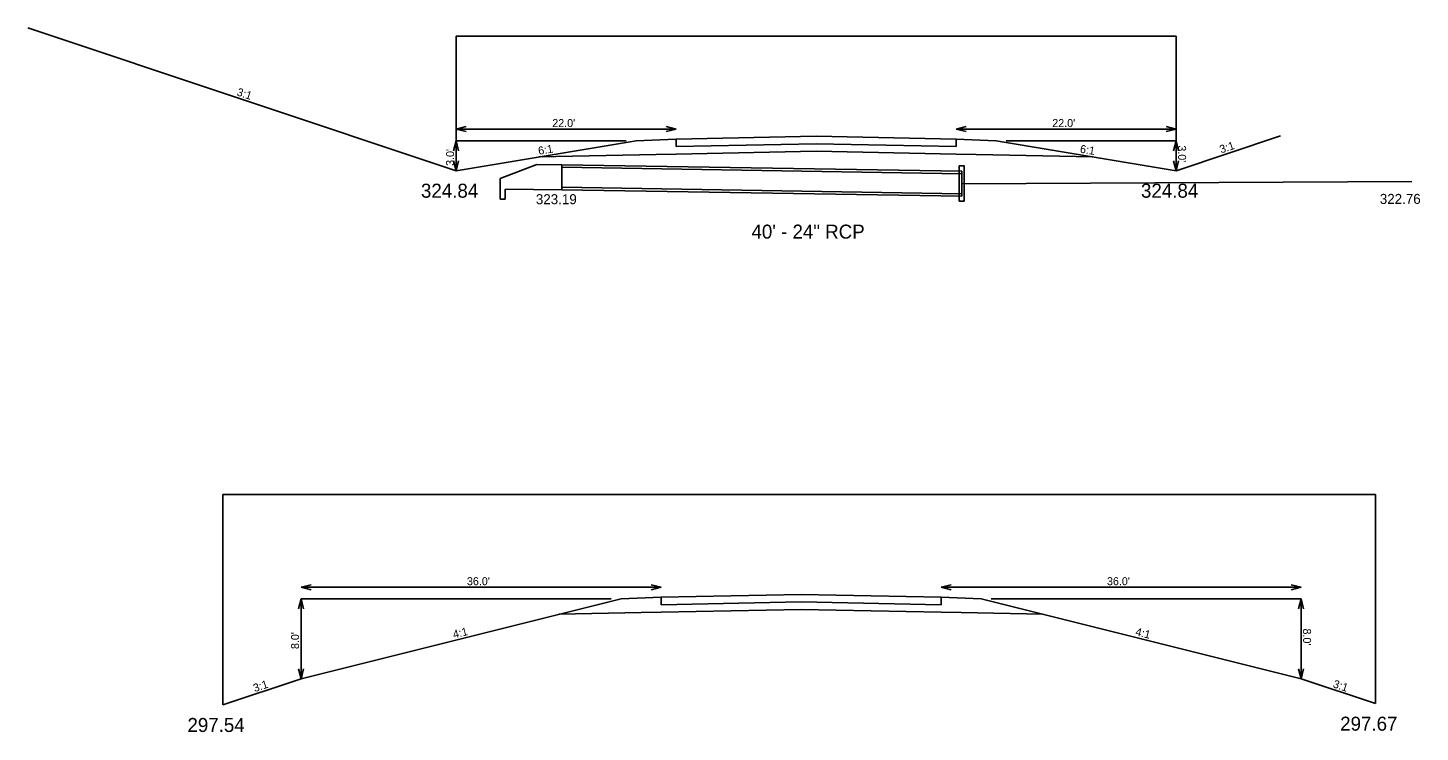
# Model space of a CAD drawing. Extents: x 2432865 to 2441203, y 1814550 to 1826842.
# Drawn here: x 2441063.6 to 2441202.8, y 1814889.3 to 1814959.7 of the extents above; entities that cross this region are included whole.
import ezdxf

# ---------------------------------------------------------------- set-up
doc = ezdxf.new("R2010")
doc.units = 0
for name, color, linetype in [('Default', 7, 'Continuous'), ('X_DRAINAGE_PIPES', 7, 'Continuous'), ('XS_M_DITCH', 7, 'Continuous'), ('XS_P_DRAINAGE', 7, 'Continuous'), ('XS_P_FINISHED_GRADE', 7, 'Continuous'), ('XS_P_SUBGRADE_GRANULAR', 7, 'Continuous'), ('XS_P_SUBGRADE_PAVEMENT', 7, 'Continuous'), ('XS_P_TX_CLEARZONE', 7, 'Continuous'), ('XS_P_TX_DCH', 7, 'Continuous'), ('XS_P_TX_FS_BS', 7, 'Continuous')]:
    doc.layers.add(name, color=color, linetype=linetype)

msp = doc.modelspace()

# ---------------------------------------------------------------- linework, layer by layer
at = {"layer": 'X_DRAINAGE_PIPES'}
msp.add_line((2441201.95, 1814944.3), (2441156.93, 1814944.08), dxfattribs=at)
at = {"layer": 'XS_M_DITCH'}
for p, q in [((2441106.37, 1814945.38), (2441106.37, 1814958.82)), ((2441106.37, 1814958.82), (2441178.37, 1814958.82)), ((2441106.37, 1814945.38), (2441106.37, 1814958.82)), ((2441106.37, 1814958.82), (2441178.37, 1814958.82)), ((2441178.37, 1814958.82), (2441178.37, 1814945.38)), ((2441178.37, 1814958.82), (2441178.37, 1814945.38)), ((2441083.04, 1814891.98), (2441083.04, 1814913.03)), ((2441083.04, 1814913.03), (2441198.3, 1814913.03)), ((2441083.04, 1814891.98), (2441083.04, 1814913.03)), ((2441083.04, 1814913.03), (2441198.3, 1814913.03)), ((2441198.3, 1814913.03), (2441198.3, 1814892.11)), ((2441198.3, 1814913.03), (2441198.3, 1814892.11))]:
    msp.add_line(p, q, dxfattribs=at)
at = {"layer": 'XS_P_DRAINAGE'}
for p, q in [((2441110.78, 1814944.6), (2441114.45, 1814946)), ((2441114.45, 1814946), (2441116.95, 1814945.98)), ((2441116.95, 1814945.98), (2441116.94, 1814943.48)), ((2441116.95, 1814945.98), (2441116.94, 1814943.48)), ((2441116.95, 1814945.98), (2441156.95, 1814945.33)), ((2441116.95, 1814945.73), (2441156.94, 1814945.08)), ((2441156.95, 1814945.33), (2441156.94, 1814942.83)), ((2441110.77, 1814942.52), (2441110.78, 1814944.6)), ((2441116.94, 1814943.73), (2441156.94, 1814943.08)), ((2441111.27, 1814942.52), (2441110.77, 1814942.52)), ((2441116.94, 1814943.48), (2441111.27, 1814943.52)), ((2441111.27, 1814943.52), (2441111.27, 1814942.52)), ((2441116.94, 1814943.48), (2441156.94, 1814942.83))]:
    msp.add_line(p, q, dxfattribs=at)
msp.add_lwpolyline([(2441156.68, 1814945.85), (2441157.18, 1814945.85), (2441157.18, 1814942.34), (2441156.68, 1814942.34)], close=True, dxfattribs=at)
at = {"layer": 'XS_P_FINISHED_GRADE'}
for p, q in [((2441106.37, 1814945.38), (2441063.55, 1814959.66)), ((2441106.37, 1814945.38), (2441063.55, 1814959.66)), ((2441124.37, 1814948.38), (2441106.37, 1814945.38)), ((2441124.37, 1814948.38), (2441106.37, 1814945.38)), ((2441128.37, 1814948.54), (2441124.37, 1814948.38)), ((2441128.37, 1814948.54), (2441124.37, 1814948.38)), ((2441128.37, 1814948.54), (2441142.37, 1814948.82)), ((2441128.37, 1814948.54), (2441142.37, 1814948.82)), ((2441142.37, 1814948.82), (2441156.37, 1814948.54)), ((2441142.37, 1814948.82), (2441156.37, 1814948.54)), ((2441156.37, 1814948.54), (2441160.37, 1814948.38)), ((2441156.37, 1814948.54), (2441160.37, 1814948.38)), ((2441160.37, 1814948.38), (2441178.37, 1814945.38)), ((2441160.37, 1814948.38), (2441178.37, 1814945.38)), ((2441178.37, 1814945.38), (2441188.81, 1814948.86)), ((2441178.37, 1814945.38), (2441188.81, 1814948.86)), ((2441122.87, 1814902.59), (2441090.87, 1814894.59)), ((2441122.87, 1814902.59), (2441090.87, 1814894.59)), ((2441126.87, 1814902.75), (2441122.87, 1814902.59)), ((2441126.87, 1814902.75), (2441122.87, 1814902.59)), ((2441126.87, 1814902.75), (2441140.87, 1814903.03)), ((2441126.87, 1814902.75), (2441140.87, 1814903.03)), ((2441140.87, 1814903.03), (2441154.87, 1814902.75)), ((2441140.87, 1814903.03), (2441154.87, 1814902.75)), ((2441154.87, 1814902.75), (2441158.87, 1814902.59)), ((2441154.87, 1814902.75), (2441158.87, 1814902.59)), ((2441158.87, 1814902.59), (2441190.87, 1814894.59)), ((2441158.87, 1814902.59), (2441190.87, 1814894.59)), ((2441090.87, 1814894.59), (2441083.04, 1814891.98)), ((2441090.87, 1814894.59), (2441083.04, 1814891.98)), ((2441190.87, 1814894.59), (2441198.3, 1814892.11)), ((2441190.87, 1814894.59), (2441198.3, 1814892.11))]:
    msp.add_line(p, q, dxfattribs=at)
at = {"layer": 'XS_P_SUBGRADE_GRANULAR'}
for p, q in [((2441126.37, 1814947), (2441114.69, 1814946.77)), ((2441126.37, 1814947), (2441114.69, 1814946.77)), ((2441128.37, 1814947.04), (2441126.37, 1814947)), ((2441128.37, 1814947.04), (2441126.37, 1814947)), ((2441128.37, 1814947.04), (2441142.37, 1814947.32)), ((2441128.37, 1814947.04), (2441142.37, 1814947.32)), ((2441142.37, 1814947.32), (2441156.37, 1814947.04)), ((2441142.37, 1814947.32), (2441156.37, 1814947.04)), ((2441156.37, 1814947.04), (2441158.37, 1814947)), ((2441156.37, 1814947.04), (2441158.37, 1814947)), ((2441158.37, 1814947), (2441170.06, 1814946.77)), ((2441158.37, 1814947), (2441170.06, 1814946.77)), ((2441124.87, 1814901.21), (2441116.69, 1814901.05)), ((2441124.87, 1814901.21), (2441116.69, 1814901.05)), ((2441126.87, 1814901.25), (2441124.87, 1814901.21)), ((2441126.87, 1814901.25), (2441124.87, 1814901.21)), ((2441126.87, 1814901.25), (2441140.87, 1814901.53)), ((2441126.87, 1814901.25), (2441140.87, 1814901.53)), ((2441140.87, 1814901.53), (2441154.87, 1814901.25)), ((2441140.87, 1814901.53), (2441154.87, 1814901.25)), ((2441154.87, 1814901.25), (2441156.87, 1814901.21)), ((2441154.87, 1814901.25), (2441156.87, 1814901.21)), ((2441156.87, 1814901.21), (2441165.04, 1814901.05)), ((2441156.87, 1814901.21), (2441165.04, 1814901.05))]:
    msp.add_line(p, q, dxfattribs=at)
at = {"layer": 'XS_P_SUBGRADE_PAVEMENT'}
for p, q in [((2441128.37, 1814947.79), (2441128.37, 1814948.54)), ((2441128.37, 1814947.79), (2441128.37, 1814948.54)), ((2441128.37, 1814947.79), (2441142.37, 1814948.07)), ((2441128.37, 1814947.79), (2441142.37, 1814948.07)), ((2441142.37, 1814948.07), (2441156.37, 1814947.79)), ((2441142.37, 1814948.07), (2441156.37, 1814947.79)), ((2441156.37, 1814947.79), (2441156.37, 1814948.54)), ((2441156.37, 1814947.79), (2441156.37, 1814948.54)), ((2441126.87, 1814902), (2441126.87, 1814902.75)), ((2441126.87, 1814902), (2441126.87, 1814902.75)), ((2441126.87, 1814902), (2441140.87, 1814902.28)), ((2441126.87, 1814902), (2441140.87, 1814902.28)), ((2441140.87, 1814902.28), (2441154.87, 1814902)), ((2441140.87, 1814902.28), (2441154.87, 1814902)), ((2441154.87, 1814902), (2441154.87, 1814902.75)), ((2441154.87, 1814902), (2441154.87, 1814902.75))]:
    msp.add_line(p, q, dxfattribs=at)
at = {"layer": 'XS_P_TX_CLEARZONE'}
for p, q in [((2441106.37, 1814949.54), (2441107.37, 1814949.79)), ((2441106.37, 1814949.54), (2441107.37, 1814949.79)), ((2441106.37, 1814949.54), (2441107.37, 1814949.29)), ((2441128.37, 1814949.54), (2441106.37, 1814949.54)), ((2441106.37, 1814949.54), (2441107.37, 1814949.29)), ((2441128.37, 1814949.54), (2441106.37, 1814949.54)), ((2441128.37, 1814949.54), (2441127.37, 1814949.79)), ((2441128.37, 1814949.54), (2441127.37, 1814949.79)), ((2441128.37, 1814949.54), (2441127.37, 1814949.29)), ((2441128.37, 1814949.54), (2441127.37, 1814949.29)), ((2441156.37, 1814949.54), (2441157.37, 1814949.79)), ((2441156.37, 1814949.54), (2441157.37, 1814949.79)), ((2441156.37, 1814949.54), (2441157.37, 1814949.29)), ((2441156.37, 1814949.54), (2441178.37, 1814949.54)), ((2441156.37, 1814949.54), (2441157.37, 1814949.29)), ((2441156.37, 1814949.54), (2441178.37, 1814949.54)), ((2441178.37, 1814949.54), (2441177.37, 1814949.79)), ((2441178.37, 1814949.54), (2441177.37, 1814949.79)), ((2441178.37, 1814949.54), (2441177.37, 1814949.29)), ((2441178.37, 1814949.54), (2441177.37, 1814949.29)), ((2441106.37, 1814948.38), (2441106.12, 1814947.38)), ((2441106.37, 1814948.38), (2441106.12, 1814947.38)), ((2441106.37, 1814948.38), (2441106.62, 1814947.38)), ((2441106.37, 1814948.38), (2441106.37, 1814945.38)), ((2441123.37, 1814948.38), (2441106.37, 1814948.38)), ((2441106.37, 1814948.38), (2441106.62, 1814947.38)), ((2441106.37, 1814948.38), (2441106.37, 1814945.38)), ((2441123.37, 1814948.38), (2441106.37, 1814948.38)), ((2441161.37, 1814948.38), (2441178.37, 1814948.38)), ((2441161.37, 1814948.38), (2441178.37, 1814948.38)), ((2441178.37, 1814948.38), (2441178.12, 1814947.38)), ((2441178.37, 1814948.38), (2441178.12, 1814947.38)), ((2441178.37, 1814948.38), (2441178.37, 1814945.38)), ((2441178.37, 1814948.38), (2441178.62, 1814947.38)), ((2441178.37, 1814948.38), (2441178.37, 1814945.38)), ((2441178.37, 1814948.38), (2441178.62, 1814947.38)), ((2441106.37, 1814945.38), (2441106.12, 1814946.38)), ((2441106.37, 1814945.38), (2441106.12, 1814946.38)), ((2441106.37, 1814945.38), (2441106.62, 1814946.38)), ((2441106.37, 1814945.38), (2441106.62, 1814946.38)), ((2441178.37, 1814945.38), (2441178.12, 1814946.38)), ((2441178.37, 1814945.38), (2441178.12, 1814946.38)), ((2441178.37, 1814945.38), (2441178.62, 1814946.38)), ((2441178.37, 1814945.38), (2441178.62, 1814946.38)), ((2441090.87, 1814903.75), (2441091.87, 1814904)), ((2441090.87, 1814903.75), (2441091.87, 1814904)), ((2441090.87, 1814903.75), (2441091.87, 1814903.5)), ((2441126.87, 1814903.75), (2441090.87, 1814903.75)), ((2441090.87, 1814903.75), (2441091.87, 1814903.5)), ((2441126.87, 1814903.75), (2441090.87, 1814903.75)), ((2441126.87, 1814903.75), (2441125.87, 1814904)), ((2441126.87, 1814903.75), (2441125.87, 1814904)), ((2441126.87, 1814903.75), (2441125.87, 1814903.5)), ((2441126.87, 1814903.75), (2441125.87, 1814903.5)), ((2441154.87, 1814903.75), (2441155.87, 1814904)), ((2441154.87, 1814903.75), (2441155.87, 1814904)), ((2441154.87, 1814903.75), (2441155.87, 1814903.5)), ((2441154.87, 1814903.75), (2441190.87, 1814903.75)), ((2441154.87, 1814903.75), (2441155.87, 1814903.5)), ((2441154.87, 1814903.75), (2441190.87, 1814903.75)), ((2441190.87, 1814903.75), (2441189.87, 1814904)), ((2441190.87, 1814903.75), (2441189.87, 1814904)), ((2441190.87, 1814903.75), (2441189.87, 1814903.5)), ((2441190.87, 1814903.75), (2441189.87, 1814903.5)), ((2441090.87, 1814902.59), (2441090.62, 1814901.59)), ((2441090.87, 1814902.59), (2441090.62, 1814901.59)), ((2441090.87, 1814902.59), (2441091.12, 1814901.59)), ((2441090.87, 1814902.59), (2441090.87, 1814894.59)), ((2441121.87, 1814902.59), (2441090.87, 1814902.59)), ((2441090.87, 1814902.59), (2441091.12, 1814901.59)), ((2441090.87, 1814902.59), (2441090.87, 1814894.59)), ((2441121.87, 1814902.59), (2441090.87, 1814902.59)), ((2441159.87, 1814902.59), (2441190.87, 1814902.59)), ((2441159.87, 1814902.59), (2441190.87, 1814902.59)), ((2441190.87, 1814902.59), (2441190.62, 1814901.59)), ((2441190.87, 1814902.59), (2441190.62, 1814901.59)), ((2441190.87, 1814902.59), (2441190.87, 1814894.59)), ((2441190.87, 1814902.59), (2441191.12, 1814901.59)), ((2441190.87, 1814902.59), (2441190.87, 1814894.59)), ((2441190.87, 1814902.59), (2441191.12, 1814901.59)), ((2441090.87, 1814894.59), (2441090.62, 1814895.59)), ((2441090.87, 1814894.59), (2441090.62, 1814895.59)), ((2441090.87, 1814894.59), (2441091.12, 1814895.59)), ((2441090.87, 1814894.59), (2441091.12, 1814895.59)), ((2441190.87, 1814894.59), (2441190.62, 1814895.59)), ((2441190.87, 1814894.59), (2441190.62, 1814895.59)), ((2441190.87, 1814894.59), (2441191.12, 1814895.59)), ((2441190.87, 1814894.59), (2441191.12, 1814895.59))]:
    msp.add_line(p, q, dxfattribs=at)

# ---------------------------------------------------------------- texts
at = {"layer": 'Default'}
for s, p in [('323.19', (2441114.35, 1814942.03)), ('322.76', (2441198.74, 1814942.06))]:
    msp.add_text(s, height=1, dxfattribs=at).set_placement(p)
at = {"layer": 'XS_P_DRAINAGE'}
msp.add_text('40\' - 24" RCP', height=1.4, dxfattribs=at).set_placement((2441135.91, 1814938.59))
at = {"layer": 'XS_P_TX_CLEARZONE'}
for s, p in [("22.0'", (2441115.99, 1814949.74)), ("22.0'", (2441115.99, 1814949.74)), ("22.0'", (2441165.99, 1814949.74)), ("22.0'", (2441165.99, 1814949.74)), ("36.0'", (2441107.46, 1814903.95)), ("36.0'", (2441107.46, 1814903.95)), ("36.0'", (2441171.46, 1814903.95)), ("36.0'", (2441171.46, 1814903.95))]:
    msp.add_text(s, height=0.8, dxfattribs=at).set_placement(p)
for s, rotation, p in [("3.0'", 90, (2441106.17, 1814945.86)), ("3.0'", 90, (2441106.17, 1814945.86)), ("3.0'", 270, (2441178.57, 1814947.91)), ("3.0'", 270, (2441178.57, 1814947.91)), ("8.0'", 90, (2441090.67, 1814897.57)), ("8.0'", 90, (2441090.67, 1814897.57)), ("8.0'", 270, (2441191.07, 1814899.62)), ("8.0'", 270, (2441191.07, 1814899.62))]:
    msp.add_text(s, height=0.8, rotation=rotation, dxfattribs=at).set_placement(p)
at = {"layer": 'XS_P_TX_DCH'}
for s, p in [('324.84', (2441102.86, 1814942.68)), ('324.84', (2441102.86, 1814942.68)), ('324.84', (2441174.86, 1814942.68)), ('324.84', (2441174.86, 1814942.68)), ('297.67', (2441194.78, 1814889.41)), ('297.67', (2441194.78, 1814889.41)), ('297.54', (2441079.51, 1814889.28)), ('297.54', (2441079.51, 1814889.28))]:
    msp.add_text(s, height=1.4, dxfattribs=at).set_placement(p)
at = {"layer": 'XS_P_TX_FS_BS'}
for s, rotation, p in [('3:1', 341.5651, (2441084.38, 1814952.92)), ('3:1', 341.5651, (2441084.38, 1814952.92)), ('6:1', 9.4623, (2441114.65, 1814946.96)), ('6:1', 9.4623, (2441114.65, 1814946.96)), ('6:1', 350.5377, (2441168.72, 1814947.19)), ('6:1', 350.5377, (2441168.72, 1814947.19)), ('3:1', 18.4349, (2441182.88, 1814947.1)), ('3:1', 18.4349, (2441182.88, 1814947.1)), ('4:1', 14.0362, (2441106.16, 1814898.62)), ('4:1', 14.0362, (2441106.16, 1814898.62)), ('4:1', 345.9638, (2441174.25, 1814898.95)), ('4:1', 345.9638, (2441174.25, 1814898.95)), ('3:1', 18.4349, (2441086.24, 1814893.26)), ('3:1', 18.4349, (2441086.24, 1814893.26)), ('3:1', 341.5651, (2441194, 1814893.76)), ('3:1', 341.5651, (2441194, 1814893.76))]:
    msp.add_text(s, height=0.8, rotation=rotation, dxfattribs=at).set_placement(p)

doc.saveas('drawing.dxf')
